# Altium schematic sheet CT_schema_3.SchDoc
size 284 x 211 mm
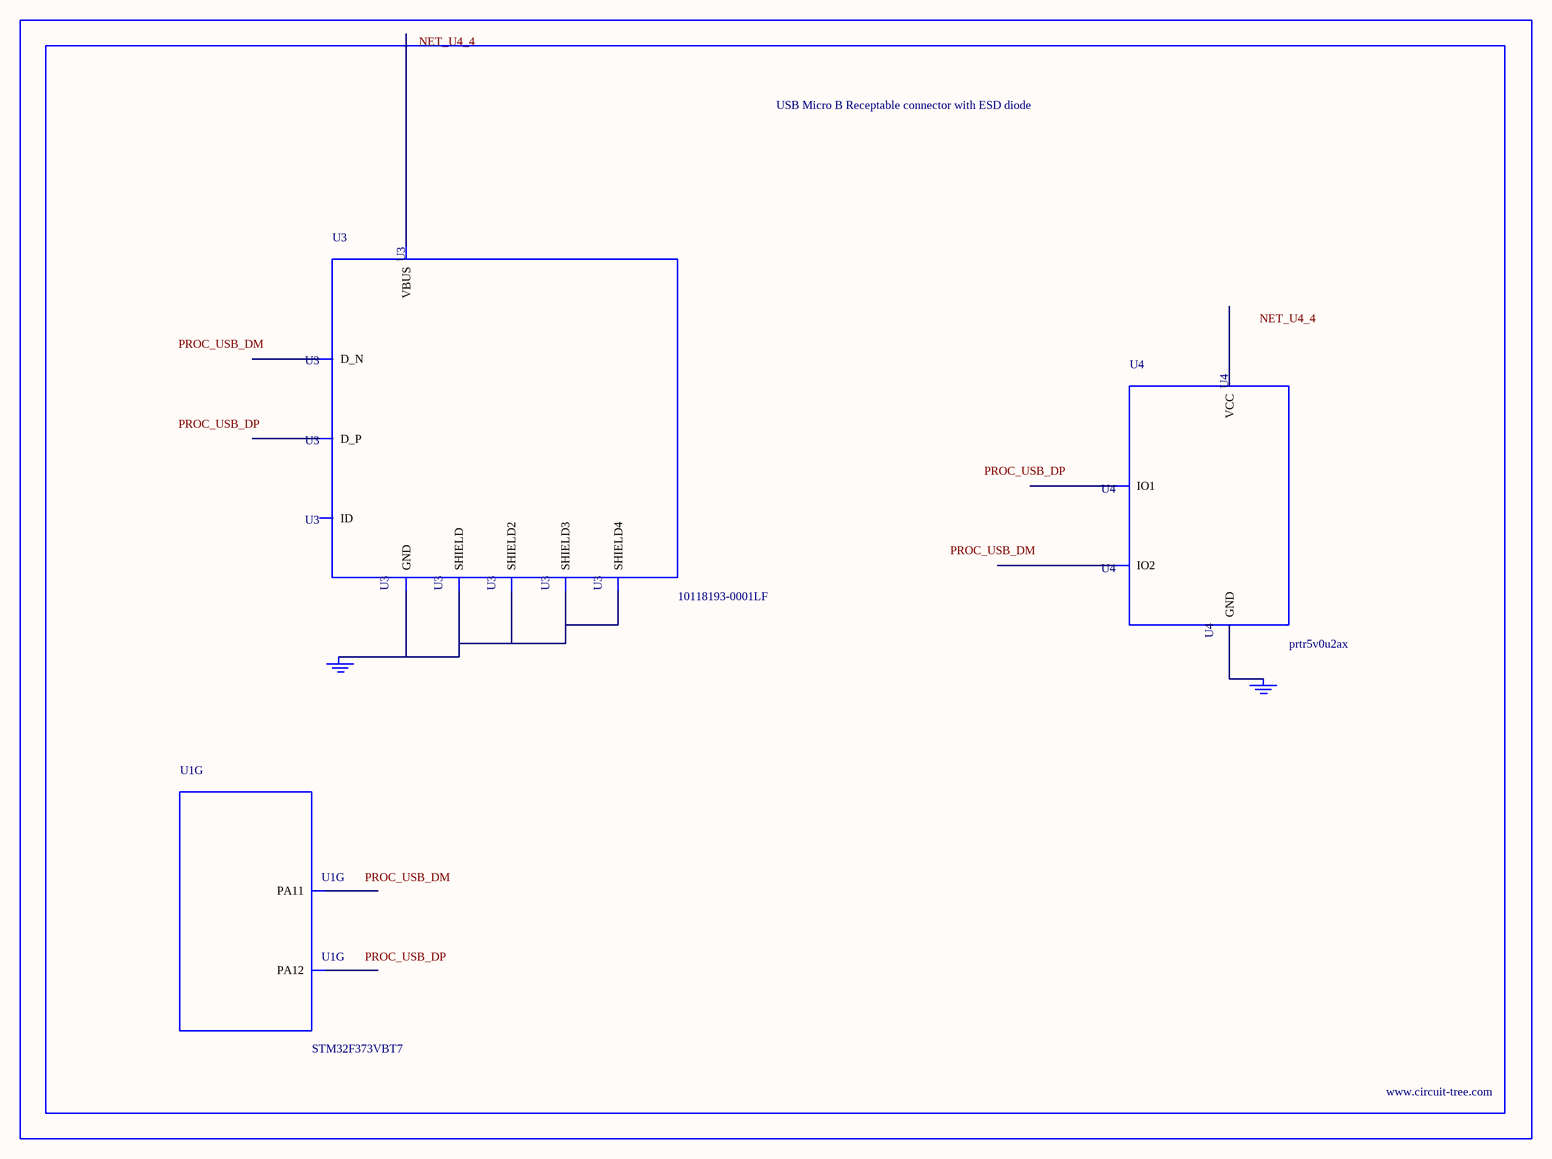
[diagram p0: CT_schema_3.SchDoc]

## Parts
BORDER2  (no value)
GND_INSTANCE_2_0  (no value)
GND_INSTANCE_2_1  (no value)
U1  STM32F373VBT7  [LQFP100]  (part G of 9)
U3  10118193-0001LF  [FCI_10118193-0001LF]
U4  prtr5v0u2ax  [SOT143B]

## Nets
NetGND_INSTANCE_2_0_0: GND_INSTANCE_2_0.0(GND) U3.5(GND) U3.6(SHIELD) U3.7(SHIELD2) U3.8(SHIELD3) U3.9(SHIELD4)
NetGND_INSTANCE_2_1_0: GND_INSTANCE_2_1.0(GND) U4.1(GND)

Not connected (* = marked no-connect by the designer): U1 70(PA11) 71(PA12); U3 1(VBUS) 2(D_N) 3(D_P) 4(ID); U4 2(IO1) 3(IO2) 4(VCC)

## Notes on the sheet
- Labels drawn without touching a wire or pin: NET_U4_4, PROC_USB_DM, PROC_USB_DP

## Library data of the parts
BORDER2 = BORDER_PAGE2
GND_INSTANCE_2_0 GND_INSTANCE_2_1 = GND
